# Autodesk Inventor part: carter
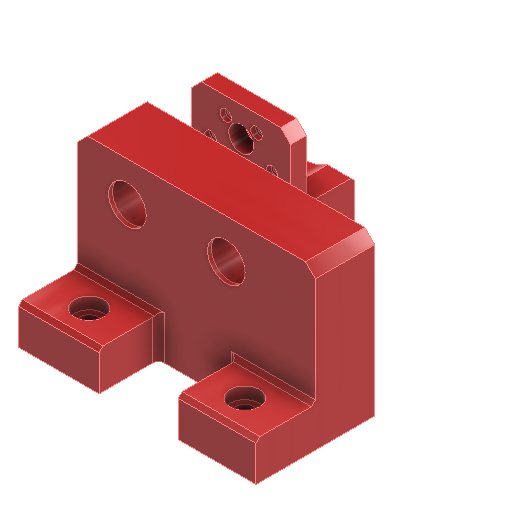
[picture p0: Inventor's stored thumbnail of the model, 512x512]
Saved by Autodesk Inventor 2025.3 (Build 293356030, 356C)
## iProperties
Created: 2026-09
Part Number: carter
Material: Plastica PET
Document SubType Name: Modeling
Designer: R5800u
Density: 1.541 g/cm^3
Appearance: Rosso
Author: R5800u
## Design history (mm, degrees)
sketch "Schizzo1"
  geometry: L1 (-75, 20)-(45, 20); L2 (45, 20)-(45, -40); L3 (45, -40)-(-75, -40); L4 (-75, -40)-(-75, 20); C1 r 11 at (0, 0); C2 r 11 at (-50, 0); 1 further point
  constraints: 8 end point, 2 centre point, 2 parallel, 1 coincident, 1 horizontal, 1 perpendicular
  dimensions: "d0" = 22 diameter of C1; "d1" = 22 diameter of C2; "d2" = 50 distance of point (0, 0) C2.centre; "d3" = 40 distance from line of point (0, 0) L3; "d4" = 45 distance from line of point (0, 0) L2; "d5" = 120 distance of L2.end L3.end; "d8" = 60 distance of L3.end L1.start
extrude "Estrusione1" new body sketch "Schizzo1" distance "d6" = 30; taper "d7" = 0 deg
sketch "Schizzo2"
  geometry: L1 (0, 0)-(120, 0) reference; L2 (0, 0)-(120, 0); L3 (120, 0)-(120, 60); L4 (120, 60)-(0, 60); L5 (0, 60)-(0, 0); 2 further points
  constraints: 8 end point, 2 parallel, 1 horizontal, 1 perpendicular
  dimensions: "d9" = 60 distance of L3.end L2.end
extrude "Estrusione2" join sketch "Schizzo2" distance "d10" = 20; taper "d11" = 0 deg
chamfer "Smusso2" distance "d15" = 2; stored, may be unused: second distance "d16" = 2, angle "d17" = 45 deg
sketch "Schizzo3"
  geometry: L1 (120, -30)-(0, -30) reference; L2 (99.309, -30)-(99.309, -60); L3 (120, -60)-(0, -60) reference; 2 further points
  constraints: 2 end point, 2 point on line, 1 midpoint, 1 vertical
hole "Foro1" sketch "Schizzo3" at (99.309, -45) diameter "d18" = 9; stored, may be unused: countersink angle "d22" = 90 deg, drill point angle "d24" = 118 deg; dims "d19" = 6, "d20" = 15, "d21" = 6, "d23" = 8
node "Piano di lavoro1"
mirror "Speculare1"
sketch "Schizzo4"
  geometry: C1 r 11 at (-50, 0) reference; C2 r 11 at (0, 0) reference; C3 r 9.5 at (-50, 0); C4 r 9.5 at (0, 0); 1 further point
  constraints: 2 centre point
  dimensions: "d25" = 1.5 radial gap between concentric circles of C1 C3; "d26" = 1.5 radial gap between concentric circles of C2 C4
extrude "Estrusione3" join sketch "Schizzo4" distance "d27" = 2; taper "d28" = 0 deg
sketch "Schizzo5"
  geometry: L1 (0, 0)-(75, 0); L2 (75, 20)-(75, -60) reference; L3 (25, 0)-(25, -60); L4 (75, -60)-(-45, -60) reference; L5 (25, -20)-(75, -20); C1 r 18.5 at (50, -7) reference; C2 r 9.5 at (0, 0) reference; 4 further points
  constraints: 6 end point, 4 point on line, 1 horizontal, 1 midpoint, 1 perpendicular
  dimensions: "d29" = 50 distance between parallel lines of L2 L3
extrude "Estrusione4" join sketch "Schizzo5" distance "d30" = 60; taper "d31" = 0 deg
node "Piano di lavoro2"
sketch "Schizzo6"
  geometry: L1 (-25, -53)-(-25, -13) reference; L2 (-25, -13)-(25, -13); L3 (25, -13)-(25, 22); L4 (25, 22)-(-25, 22); L5 (-25, 22)-(-25, -13); C1 r 18.5 at (0, 0) reference; C2 r 1.6 at (-7.75, 13.423) reference; C3 r 1.6 at (7.75, 13.423) reference; C4 r 1.6 at (-15.5, 0) reference; C5 r 1.6 at (15.5, 0) reference; C6 r 6.25 at (0, 7) reference; 3 further points
  constraints: 8 end point, 2 parallel, 1 horizontal, 1 perpendicular
  dimensions: "d34" = 35 distance of L3.end L2.end
extrude "Estrusione5" join sketch "Schizzo6" distance "d32" = 8; taper "d33" = 0 deg
chamfer "Smusso3" distance "d35" = 10; stored, may be unused: second distance "d36" = 2, angle "d37" = 45 deg
chamfer "Smusso4" distance "d38" = 5; stored, may be unused: second distance "d39" = 2, angle "d40" = 45 deg
sketch "Schizzo7"
  geometry: C1 r 1.6 at (-7.75, 13.423) reference; C2 r 1.6 at (7.75, 13.423) reference; C3 r 1.6 at (-15.5, 0) reference; C4 r 1.6 at (15.5, 0) reference; 5 further points
  constraints: 4 coincident
hole "Foro2" sketch "Schizzo7" at (-7.75, 13.423), (7.75, 13.423), (-15.5, 0), (15.5, 0) diameter "d41" = 3.4; stored, may be unused: countersink angle "d45" = 90 deg, drill point angle "d47" = 118 deg; dims "d42" = 6, "d43" = 5.8, "d44" = 2.4, "d46" = 8
sketch "Schizzo8"
  geometry: L1 (50, 0)-(120, 0) reference; L2 (120, 0)-(120, 60) reference; L3 (120, 60)-(0, 60) reference; L4 (0, 60)-(0, -60) reference; L5 (50, -60)-(0, -60) reference; L6 (50, 0)-(50, -60) reference; L7 (0, 0)-(50, 0); L8 (0, -5)-(50, -5); L9 (5, -55)-(5, 55); L10 (5, 55)-(115, 55); L11 (115, 55)-(115, 5); L12 (115, 5)-(45, 5); L13 (45, 5)-(45, -55); L14 (45, -55)-(5, -55); C1 r 4.5 at (20.691, 45) reference; C2 r 4.5 at (99.309, 45) reference; 3 further points
  constraints: 16 end point, 1 horizontal, 1 midpoint, 1 parallel, 5 other
  dimensions: "d48" = 5 distance between parallel lines of L7 L8; "d49" = 5 distance between parallel lines of L4 L9
extrude "Estrusione6" cut sketch "Schizzo8" distance "d50" = 30; taper "d51" = 0 deg
fillet "Raccordo1" dims "d52" = 20
chamfer "Smusso5" distance "d53" = 2; stored, may be unused: second distance "d54" = 2, angle "d55" = 45 deg
node "Piano di lavoro4"
sketch "Schizzo9"
  geometry: C1 r 12 at (0, 0); C2 r 11 at (0, 0) reference; 1 further point
  constraints: 1 centre point, 1 coincident
  dimensions: "d58" = 24 diameter of C1
extrude "Estrusione7" cut sketch "Schizzo9" distance "d59" = 1; taper "d60" = 0 deg
sketch "Schizzo10"
  geometry: C1 r 11 at (50, 0) reference; C2 r 11 at (50, 0) reference; C3 r 11.5 at (50, 0); 1 further point
  constraints: 1 centre point
  dimensions: "d61" = 0.5 radial gap between concentric circles of C1 C3
extrude "Estrusione8" cut sketch "Schizzo10" distance "d62" = 1; taper "d63" = 0 deg
chamfer "Smusso6" distance "d64" = 5; stored, may be unused: second distance "d65" = 2, angle "d66" = 45 deg
sketch "Schizzo11"
  geometry: 1 further point
sketch "Schizzo12"
  geometry: L1 (114, 6)-(6, 6); L2 (6, 6)-(6, 24); L3 (6, 24)-(114, 24); L4 (114, 24)-(114, 6); L5 (55, 0)-(120, 0) reference; L6 (120, 0)-(120, 60) reference; L7 (0, 60)-(0, -60) reference; 1 further point
  constraints: 8 end point, 2 parallel, 1 horizontal, 1 perpendicular
  dimensions: "d67" = 6 distance between parallel lines of L5 L1; "d68" = 18 distance of L3.end L1.start; "d69" = 6 distance between parallel lines of L6 L4; "d70" = 6 distance between parallel lines of L7 L2
extrude "Estrusione9" cut sketch "Schizzo12" distance "d71" = 40; taper "d72" = 0 deg
fillet "Raccordo2" dims "d73" = 9
sketch "Schizzo13"
  geometry: L1 (120, -60)-(0, -60) reference; L2 (120, -30)-(0, -30) reference; L3 (40.691, -60)-(80.691, -60); L4 (80.691, -60)-(80.691, -30); L5 (80.691, -30)-(40.691, -30); L6 (40.691, -30)-(40.691, -60); C1 r 4.5 at (20.691, -45) reference; 3 further points
  constraints: 8 end point, 2 parallel, 2 point on line, 1 horizontal, 1 perpendicular
  dimensions: "d74" = 40 distance between parallel lines of L4 L6; "d75" = 20 distance from line of C1.centre L6
extrude "Estrusione10" cut sketch "Schizzo13" stored distance "d76" = 120; taper "d77" = 0 deg
fillet "Raccordo3" dims "d78" = 3
node "Solido1"
node "Riferimento1"
node "Riferimento2"
node "Riferimento3"
node "Riferimento4"
node "Riferimento5"
node "Riferimento6"
node "Riferimento7"
node "Linea chiusa proiettata1"
node "Linea chiusa proiettata2"
other parameters: "d57" = -1
